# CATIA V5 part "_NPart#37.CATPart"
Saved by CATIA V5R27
Part number: PCB^Endstop_Opto_TCST2103_D‚faut
Revision: ANY
Definition: UNKNOWN
Nomenclature: PCB^Endstop_Opto_TCST2103_D‚faut
Source: Unknown
Bounding box of the stored display mesh (mm): x -12.25 to 20.75, y -5 to 5, z 0 to 1
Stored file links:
  E:\university\my-thesis\My Thesis Publication\Final-Updata\CAD\_NPart#37.CATPart
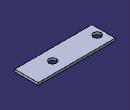
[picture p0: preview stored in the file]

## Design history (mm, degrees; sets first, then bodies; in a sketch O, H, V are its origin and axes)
Body1 "Dégagement M31" (main body)
  Solid1: solid without history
